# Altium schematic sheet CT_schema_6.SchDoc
size 250 x 188 mm
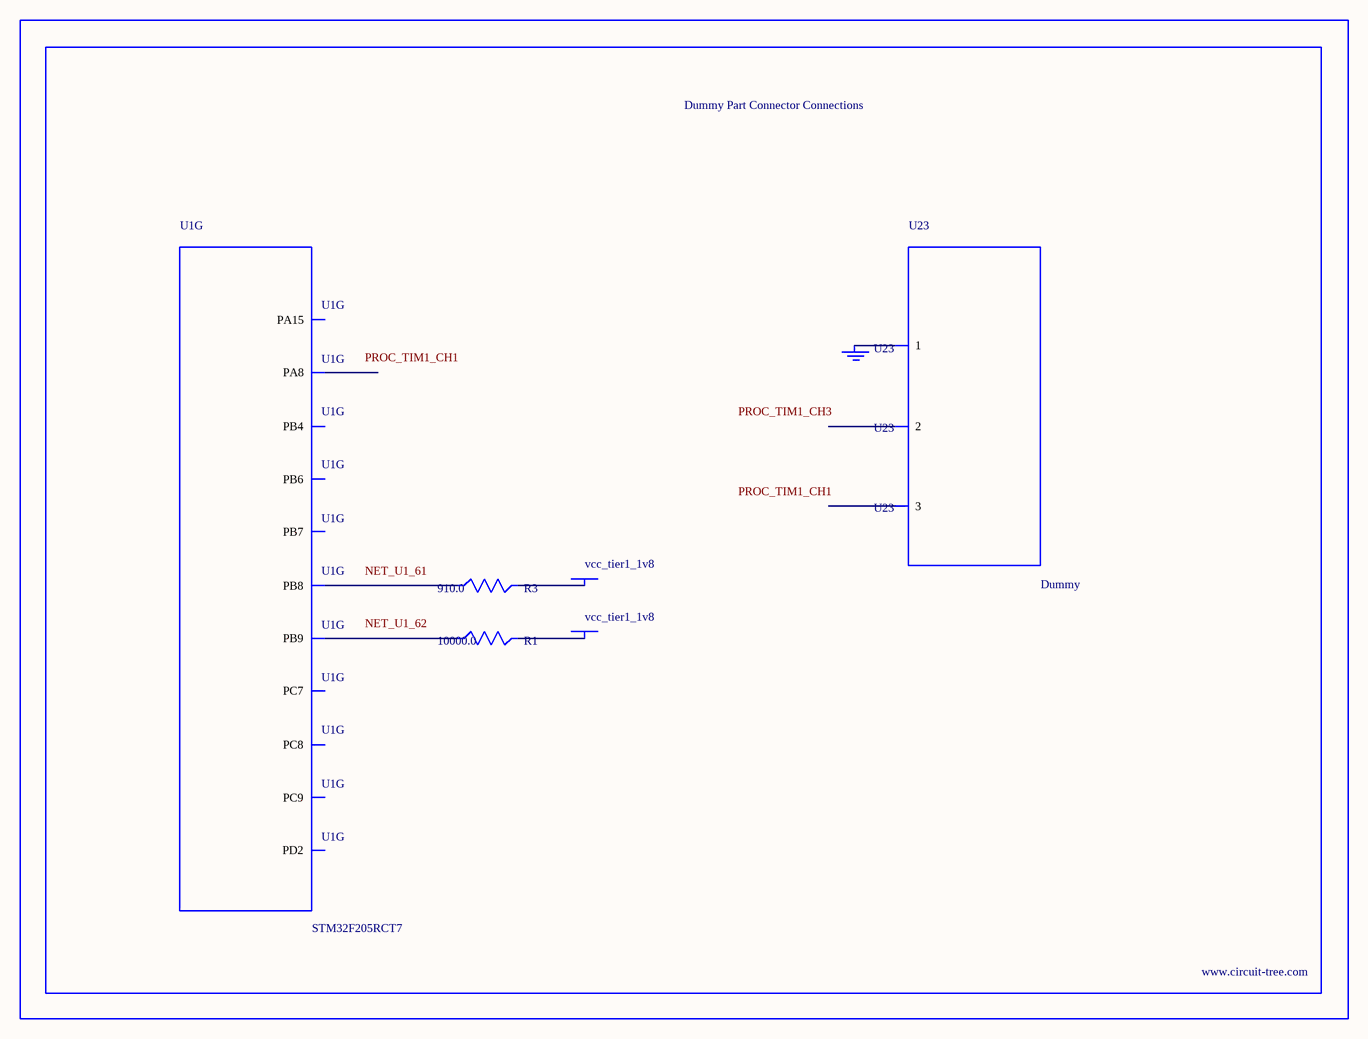
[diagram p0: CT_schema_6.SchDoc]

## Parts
BORDER5  (no value)
GND_INSTANCE_5_0  (no value)
POWER_INSTANCE_5_0  vcc_tier1_1v8
POWER_INSTANCE_5_1  vcc_tier1_1v8
R1  10000.0  [R0603]
R3  910.0  [R0603]
U1  STM32F205RCT7  [LQFP64]  (part G of 7)
U23  Dummy  [DUMMY_PACKAGE_226]

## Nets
NetGND_INSTANCE_5_0_0: GND_INSTANCE_5_0.0(GND) U23.1
NetPOWER_INSTANCE_5_0_0: POWER_INSTANCE_5_0.0(PWR) R3.2
NetPOWER_INSTANCE_5_1_0: POWER_INSTANCE_5_1.0(PWR) R1.2
NetR1_1: R1.1 U1.62(PB9)
NetR3_1: R3.1 U1.61(PB8)

Not connected (* = marked no-connect by the designer): U1 38(PC7) 39(PC8) 40(PC9) 41(PA8) 50(PA15) 54(PD2) 56(PB4) 58(PB6) 59(PB7); U23 2 3

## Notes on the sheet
- Labels drawn without touching a wire or pin: NET_U1_61, NET_U1_62, PROC_TIM1_CH1, PROC_TIM1_CH3

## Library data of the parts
BORDER5 = BORDER_PAGE5
GND_INSTANCE_5_0 = GND
POWER_INSTANCE_5_0 POWER_INSTANCE_5_1 = PWR
R1 = RC0603JR-0710KL
R3 = RC0603JR-07910RL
